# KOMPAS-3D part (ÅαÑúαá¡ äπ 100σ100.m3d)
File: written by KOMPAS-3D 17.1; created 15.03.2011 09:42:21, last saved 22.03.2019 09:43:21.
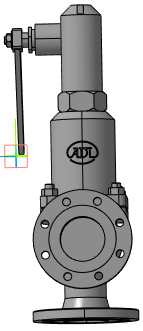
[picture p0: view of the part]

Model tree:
1. Плоскость XY
2. Плоскость ZX
3. Плоскость ZY
4. Ось X
5. Ось Y
6. Ось Z
7. Начало координат
8. Операция без истории:2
